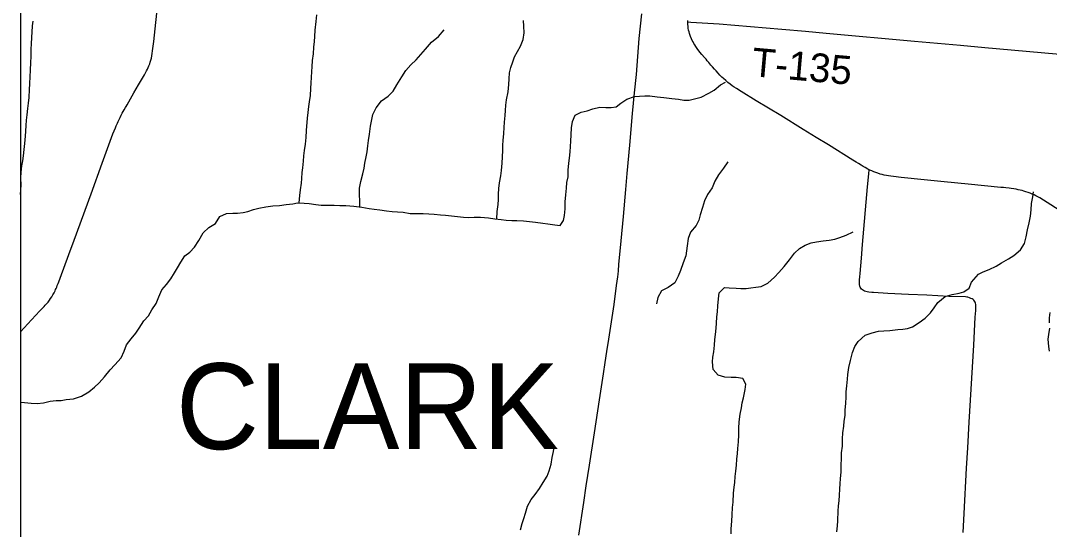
# Model space of a CAD drawing. Extents: x 0 to 48.6, y 0 to 22.
# Drawn here: x 2.1 to 4.141, y 18.455 to 19.466 of the extents above; entities that cross this region are included whole.
import ezdxf

# ---------------------------------------------------------------- set-up
doc = ezdxf.new("R2010")
doc.units = 0
for name, color, linetype in [('GM_X_Corporation', 7, 'Continuous'), ('GM_X_County_Road', 7, 'Continuous'), ('GM_X_Minor_River', 7, 'Continuous'), ('GM_X_State_Route', 7, 'Continuous'), ('GM_X_Township_Road', 7, 'Continuous'), ('GM_X_Township_Road_Text', 7, 'Continuous'), ('GM_X_Township_Text', 7, 'Continuous'), ('SH_Data', 7, 'Continuous')]:
    doc.layers.add(name, color=color, linetype=linetype)

msp = doc.modelspace()

# ---------------------------------------------------------------- linework, layer by layer
at = {"layer": 'GM_X_Corporation'}
for points in [[(8.9, 20.9), (2.1, 20.9), (2.1, 14.1)], [(5.5264, 17.0064), (5.8387, 17.2541), (6.5365, 17.7727), (6.4996, 17.9212), (6.3396, 18.6531), (6.2759, 18.9159), (6.0412, 19.8859), (5.8236, 20.7829), (5.795, 20.9), (2.1, 20.9), (2.1, 14.1)]]:
    msp.add_lwpolyline(points, dxfattribs=at)
at = {"layer": 'GM_X_County_Road'}
for points in [[(2.1, 18.8478), (2.1219, 18.8718), (2.1303, 18.881), (2.1376, 18.8886), (2.1467, 18.8983), (2.1487, 18.9004), (2.1514, 18.9035), (2.1544, 18.9069), (2.1572, 18.9107), (2.1595, 18.9138), (2.1619, 18.9174), (2.1642, 18.921), (2.1652, 18.9229), (2.1663, 18.925), (2.1686, 18.9292), (2.1695, 18.9315), (2.1705, 18.9337), (2.1716, 18.9362), (2.1729, 18.9394), (2.1745, 18.9436), (2.1757, 18.9468), (2.1786, 18.9545), (2.1958, 19.0012), (2.2062, 19.0298), (2.2401, 19.1219), (2.2618, 19.1828), (2.2832, 19.2405), (2.288, 19.2526), (2.2896, 19.2567), (2.2921, 19.2622), (2.2934, 19.265), (2.2947, 19.2681), (2.2973, 19.2732), (2.2998, 19.2781), (2.3017, 19.2816), (2.3037, 19.2852), (2.3054, 19.2883), (2.3079, 19.2928), (2.3093, 19.2953), (2.3112, 19.2985), (2.3245, 19.322), (2.334, 19.338), (2.3457, 19.3578), (2.3501, 19.366), (2.3517, 19.3693), (2.3533, 19.3726), (2.3547, 19.376), (2.3561, 19.3795), (2.3573, 19.3831), (2.3585, 19.3871), (2.3595, 19.3913), (2.3604, 19.3955), (2.3612, 19.4005), (2.362, 19.4053), (2.3641, 19.4238), (2.368, 19.4615), (2.374, 19.5171)], [(3.2071, 18.4437), (3.217, 18.5088), (3.222, 18.542), (3.2283, 18.5831), (3.2382, 18.6469), (3.2483, 18.7127), (3.2561, 18.7643), (3.2597, 18.787), (3.2628, 18.8085), (3.2667, 18.8331), (3.2771, 18.9019), (3.2823, 18.9394), (3.2845, 18.9571), (3.2851, 18.9622), (3.2857, 18.9687), (3.287, 18.9813), (3.291, 19.0284), (3.2956, 19.0766), (3.3005, 19.1304), (3.3034, 19.162), (3.3085, 19.2183), (3.3141, 19.2814), (3.318, 19.3222), (3.3215, 19.3587), (3.3273, 19.4298), (3.332, 19.4793)], [(3.9697, 18.4493), (3.9718, 18.4871), (3.9766, 18.5771), (3.979, 18.6174), (3.9818, 18.6683), (3.9906, 18.8209), (3.9936, 18.8767), (3.9946, 18.8898), (3.9948, 18.8948), (3.9949, 18.8986), (3.9946, 18.9019), (3.9941, 18.9046), (3.9933, 18.9069), (3.9923, 18.9087), (3.9907, 18.9104), (3.9893, 18.9117), (3.9874, 18.913), (3.9852, 18.9142), (3.9822, 18.9154), (3.9792, 18.9162), (3.9768, 18.9166), (3.9741, 18.9169), (3.941, 18.9181), (3.8976, 18.9204), (3.861, 18.9221), (3.82, 18.924), (3.7921, 18.9256), (3.7884, 18.9258), (3.7828, 18.9264), (3.7792, 18.9269), (3.7764, 18.9276), (3.7738, 18.9285), (3.7719, 18.9296), (3.7701, 18.9309), (3.7683, 18.9325), (3.7666, 18.9347), (3.7657, 18.9366), (3.7649, 18.9385), (3.7643, 18.9414), (3.7642, 18.9433), (3.7639, 18.9456), (3.764, 18.9487), (3.7641, 18.9512), (3.7646, 18.9567), (3.7653, 18.9635), (3.7679, 18.9938), (3.7702, 19.021), (3.78, 19.1355), (3.7827, 19.1615), (3.7835, 19.1695)]]:
    msp.add_lwpolyline(points, dxfattribs=at)
at = {"layer": 'GM_X_Minor_River'}
for points in [[(2.6523, 19.1036), (2.6537, 19.1181), (2.6554, 19.1298), (2.6571, 19.1427), (2.6579, 19.1522), (2.6585, 19.1639), (2.6597, 19.1734), (2.6611, 19.1863), (2.6616, 19.1969), (2.6632, 19.2079), (2.6649, 19.2204), (2.6662, 19.2333), (2.6672, 19.2473), (2.6694, 19.272), (2.6707, 19.2833), (2.672, 19.2951), (2.6733, 19.3046), (2.6749, 19.3167), (2.6759, 19.3311), (2.6764, 19.3421), (2.6769, 19.3527), (2.6775, 19.3645), (2.6784, 19.374), (2.6793, 19.3865), (2.681, 19.3994), (2.6815, 19.413), (2.6828, 19.4244), (2.6837, 19.4339), (2.6846, 19.4464), (2.6864, 19.4635), (2.6877, 19.4767)], [(2.1, 19.1202), (2.1008, 19.1294), (2.1009, 19.1389), (2.1007, 19.1533), (2.1013, 19.1639), (2.1026, 19.1772), (2.1046, 19.187), (2.1055, 19.1973), (2.1068, 19.2094), (2.1085, 19.2219), (2.1098, 19.2359), (2.1107, 19.2458), (2.1112, 19.2576), (2.1118, 19.2682), (2.113, 19.2784), (2.1144, 19.2913), (2.1156, 19.3015), (2.1169, 19.3129), (2.1175, 19.3289), (2.1184, 19.3402), (2.119, 19.3546), (2.1195, 19.3668), (2.1201, 19.3831), (2.1207, 19.3937), (2.1212, 19.4093), (2.1217, 19.4188), (2.1223, 19.4324), (2.1228, 19.4423), (2.1238, 19.4552), (2.125, 19.4647)], [(3.0445, 19.0717), (3.0453, 19.0864), (3.047, 19.1004), (3.0479, 19.1103), (3.048, 19.1213), (3.0485, 19.1323), (3.0502, 19.1437), (3.0523, 19.1577), (3.0539, 19.1683), (3.0553, 19.1823), (3.0562, 19.1948), (3.0567, 19.2077), (3.0569, 19.218), (3.0574, 19.2275), (3.0583, 19.2415), (3.0589, 19.2533), (3.0598, 19.2639), (3.0615, 19.2775), (3.062, 19.287), (3.0625, 19.2976), (3.0638, 19.3083), (3.067, 19.3242), (3.0687, 19.3389), (3.0689, 19.3503), (3.0698, 19.3617), (3.0722, 19.3727), (3.0762, 19.3836), (3.0797, 19.3938), (3.0856, 19.404), (3.0914, 19.4146), (3.0969, 19.4278), (3.0986, 19.4414), (3.098, 19.4547), (3.0978, 19.4657)], [(2.773, 19.0957), (2.7732, 19.1078), (2.7726, 19.1199), (2.7724, 19.1332), (2.7748, 19.1461), (2.7792, 19.1616), (2.7813, 19.1726), (2.7829, 19.1828), (2.7858, 19.1949), (2.7874, 19.2048), (2.7891, 19.2169), (2.7904, 19.2275), (2.792, 19.24), (2.7942, 19.2559), (2.7962, 19.2662), (2.799, 19.279), (2.8053, 19.2926), (2.8157, 19.3061), (2.8291, 19.3158), (2.8388, 19.3256), (2.8465, 19.338), (2.8562, 19.3538), (2.8644, 19.3666), (2.874, 19.3775), (2.8844, 19.388), (2.8937, 19.3981), (2.9029, 19.4087), (2.9153, 19.4225), (2.9287, 19.4341), (2.9399, 19.4473)], [(3.1772, 19.0688), (3.1789, 19.0786), (3.1802, 19.0919), (3.1804, 19.1059), (3.1813, 19.12), (3.1826, 19.1332), (3.1835, 19.1442), (3.1859, 19.1552), (3.1865, 19.1689), (3.1878, 19.1825), (3.1891, 19.1924), (3.19, 19.2053), (3.1909, 19.2159), (3.1914, 19.2261), (3.192, 19.239), (3.1926, 19.2527), (3.1946, 19.2652), (3.2001, 19.278), (3.212, 19.2839), (3.2238, 19.2864), (3.2348, 19.2901), (3.2493, 19.2937), (3.2607, 19.2932), (3.2713, 19.293), (3.2812, 19.2944), (3.2908, 19.3019), (3.3027, 19.3093), (3.318, 19.3148), (3.3279, 19.3158), (3.3385, 19.3161), (3.3484, 19.316), (3.3628, 19.3142), (3.3761, 19.3126), (3.3916, 19.3112), (3.4049, 19.3095), (3.4155, 19.3079), (3.4261, 19.3077), (3.4391, 19.3106), (3.4501, 19.3135), (3.4654, 19.3213), (3.4758, 19.3276), (3.4881, 19.3381), (3.498, 19.3436)], [(3.5027, 19.1853), (3.4942, 19.1725), (3.4842, 19.1597), (3.4772, 19.1469), (3.4717, 19.1333), (3.4628, 19.1205), (3.4565, 19.1077), (3.4525, 19.0948), (3.4482, 19.0801), (3.4454, 19.0695), (3.4399, 19.0585), (3.4291, 19.0458), (3.424, 19.0333), (3.4219, 19.0185), (3.4206, 19.0087), (3.4194, 18.9988), (3.4142, 18.9845), (3.4087, 18.9697), (3.4044, 18.958), (3.3978, 18.9452), (3.3847, 18.9359), (3.371, 18.9288), (3.364, 18.9156), (3.3615, 18.9035)], [(3.7354, 18.6819), (3.7359, 18.6925), (3.7368, 18.7062), (3.7374, 18.7179), (3.7379, 18.7286), (3.7392, 18.7403), (3.7401, 18.7536), (3.7406, 18.7631), (3.7431, 18.7767), (3.7463, 18.7907), (3.7499, 18.8066), (3.755, 18.8183), (3.7616, 18.8285), (3.7751, 18.8412), (3.7892, 18.846), (3.8018, 18.8492), (3.8124, 18.8498), (3.8242, 18.8504), (3.8398, 18.8521), (3.8497, 18.8532), (3.8592, 18.8545), (3.8691, 18.8575), (3.8822, 18.866), (3.894, 18.875), (3.9048, 18.8855), (3.9122, 18.8952), (3.9191, 18.9058), (3.9337, 18.9181), (3.9478, 18.9221), (3.9615, 18.9242), (3.9711, 18.9271), (3.9814, 18.9346), (3.9865, 18.9463), (4, 18.9621), (4.0096, 18.9669), (4.0214, 18.9716), (4.0352, 18.9779), (4.0459, 18.9846), (4.0593, 18.9924), (4.07, 18.9991), (4.0831, 19.0107), (4.0912, 19.0231), (4.0945, 19.0364), (4.0973, 19.0504), (4.1009, 19.064), (4.103, 19.0773), (4.1047, 19.0898), (4.1052, 19.1023), (4.1077, 19.1159), (4.1089, 19.1254)], [(2.1, 18.7078), (2.1077, 18.7072), (2.121, 18.7058), (2.1328, 18.7057), (2.1457, 18.707), (2.1587, 18.7099), (2.1708, 18.7117), (2.1807, 18.7115), (2.1902, 18.7133), (2.2051, 18.715), (2.2207, 18.7197), (2.2352, 18.7283), (2.2464, 18.738), (2.256, 18.7466), (2.2664, 18.7586), (2.2776, 18.7725), (2.2872, 18.7819), (2.2996, 18.7958), (2.3055, 18.8094), (2.3098, 18.8218), (2.3191, 18.8339), (2.3283, 18.8448), (2.3353, 18.8549), (2.3442, 18.8696), (2.3539, 18.8797), (2.3601, 18.8914), (2.369, 18.9042), (2.3741, 18.9174), (2.3804, 18.931), (2.3893, 18.9415), (2.3981, 18.9528), (2.4055, 18.9645), (2.4114, 18.975), (2.418, 18.986), (2.4257, 18.9984), (2.4357, 19.0059), (2.4453, 19.0156), (2.4539, 19.0292), (2.4624, 19.0442), (2.4736, 19.0547), (2.4866, 19.0625), (2.4951, 19.0765), (2.5085, 19.0827), (2.5207, 19.0833), (2.5305, 19.0832), (2.5412, 19.0846), (2.5507, 19.0867), (2.5622, 19.0904), (2.5725, 19.0929), (2.5865, 19.0958), (2.6002, 19.0979), (2.6139, 19.0985), (2.6269, 19.1002), (2.6398, 19.1015), (2.6493, 19.1037), (2.6626, 19.1031), (2.6725, 19.1023), (2.6857, 19.1006), (2.6964, 19.0993), (2.7222, 19.0989), (2.7332, 19.0984), (2.7453, 19.0983), (2.7613, 19.0969), (2.7772, 19.0952), (2.7912, 19.0927), (2.8011, 19.0915), (2.8125, 19.0902), (2.8257, 19.0881), (2.8371, 19.0868), (2.8477, 19.0859), (2.8587, 19.085), (2.8731, 19.0829), (2.8853, 19.0824), (2.8986, 19.0826), (2.91, 19.0817), (2.9206, 19.0812), (2.9327, 19.0803), (2.943, 19.079), (2.9547, 19.0781), (2.9665, 19.0764), (2.9783, 19.0755), (2.9893, 19.075), (2.9999, 19.0752), (3.0124, 19.0754), (3.028, 19.0741), (3.0409, 19.072), (3.0534, 19.0707), (3.0629, 19.0695), (3.0746, 19.0686), (3.0845, 19.0684), (3.0978, 19.0679), (3.1092, 19.067), (3.1213, 19.0657), (3.1357, 19.0632), (3.1456, 19.0623), (3.1596, 19.0603), (3.1706, 19.059), (3.1772, 19.0688)], [(3.5393, 18.9339), (3.5488, 18.9349), (3.5587, 18.9366), (3.569, 18.938), (3.582, 18.9443), (3.5954, 18.9559), (3.6043, 18.9657), (3.6147, 18.9777), (3.6255, 18.9908), (3.6348, 19.004), (3.6448, 19.0134), (3.6563, 19.02), (3.6681, 19.0241), (3.6788, 19.0266), (3.6917, 19.0283), (3.7039, 19.03), (3.7149, 19.0314), (3.7252, 19.0347), (3.7378, 19.0399), (3.7516, 19.0465)], [(3.5093, 18.4464), (3.5098, 18.4563), (3.5107, 18.4715), (3.5113, 18.4844), (3.5119, 18.4988), (3.5132, 18.5098), (3.5141, 18.5272), (3.5154, 18.539), (3.5167, 18.5485), (3.5176, 18.5606), (3.5189, 18.5708), (3.5202, 18.5833), (3.5207, 18.5951), (3.522, 18.6061), (3.5225, 18.6163), (3.5239, 18.6292), (3.5248, 18.6433), (3.5246, 18.6565), (3.5251, 18.6687), (3.5276, 18.6842), (3.5297, 18.6967), (3.5313, 18.7066), (3.5338, 18.7164), (3.537, 18.7334), (3.5383, 18.7437), (3.5324, 18.7551), (3.5191, 18.7568), (3.5096, 18.757), (3.4967, 18.7579), (3.4838, 18.7619), (3.4737, 18.773), (3.4724, 18.7882), (3.4733, 18.7977), (3.475, 18.8083), (3.4763, 18.8215), (3.4768, 18.8322), (3.4781, 18.8424), (3.4798, 18.8549), (3.4807, 18.8651), (3.4812, 18.8773), (3.4821, 18.8875), (3.483, 18.8993), (3.4843, 18.9129), (3.486, 18.9251), (3.496, 18.9356), (3.5055, 18.9351), (3.5192, 18.9345), (3.5287, 18.934), (3.5393, 18.9339)], [(4.1412, 18.8653), (4.1406, 18.8756), (4.1422, 18.8862)], [(4.1408, 18.8091), (4.1394, 18.8187), (4.1381, 18.8331), (4.1394, 18.8426), (4.1418, 18.8547)], [(3.719, 18.4509), (3.7203, 18.4623), (3.7212, 18.4722), (3.7215, 18.4923), (3.7223, 18.5018), (3.7236, 18.5127), (3.7241, 18.523), (3.7251, 18.5363), (3.726, 18.5457), (3.7265, 18.5567), (3.7278, 18.5689), (3.7276, 18.5844), (3.7281, 18.5951), (3.7283, 18.6072), (3.73, 18.6205), (3.7306, 18.6353), (3.7311, 18.6474), (3.7328, 18.6603), (3.7337, 18.6702), (3.7354, 18.6819)], [(3.0919, 18.4549), (3.0951, 18.467), (3.0983, 18.4768), (3.1015, 18.4878), (3.1058, 18.5014), (3.1125, 18.5146), (3.1206, 18.5247), (3.1291, 18.5368), (3.1369, 18.5484), (3.1442, 18.5609), (3.1486, 18.5718), (3.1525, 18.5851), (3.1542, 18.5983), (3.1571, 18.6101), (3.1583, 18.6199)]]:
    msp.add_lwpolyline(points, dxfattribs=at)
at = {"layer": 'GM_X_State_Route'}
msp.add_lwpolyline([(4.1604, 19.0894), (4.1362, 19.1047), (4.1219, 19.1134), (4.1179, 19.1155), (4.1137, 19.1178), (4.1103, 19.1194), (4.1065, 19.1212), (4.1024, 19.1228), (4.0985, 19.1244), (4.0939, 19.1259), (4.0902, 19.127), (4.0865, 19.128), (4.0825, 19.1291), (4.079, 19.1298), (4.0746, 19.1307), (4.0699, 19.1314), (4.0649, 19.1322), (4.0606, 19.1327), (4.0545, 19.1334), (4.0495, 19.134), (4.0442, 19.1345), (3.9796, 19.1408), (3.932, 19.1455), (3.8924, 19.1496), (3.8467, 19.1541), (3.8318, 19.1558), (3.8265, 19.1566), (3.8213, 19.1573), (3.8176, 19.158), (3.8133, 19.1588), (3.8091, 19.1598), (3.8048, 19.1609), (3.8002, 19.1624), (3.7965, 19.1637), (3.7926, 19.1653), (3.7884, 19.167), (3.7848, 19.1688), (3.7835, 19.1695), (3.7806, 19.1709), (3.7755, 19.1737), (3.7713, 19.176), (3.7674, 19.1784), (3.7618, 19.1818), (3.7574, 19.1844), (3.7508, 19.1885), (3.7027, 19.2187), (3.6783, 19.2337), (3.6524, 19.2496), (3.6079, 19.2769), (3.5591, 19.3066), (3.5293, 19.3246), (3.5198, 19.3305), (3.5153, 19.3336), (3.5115, 19.3361), (3.5074, 19.3393), (3.5031, 19.3426), (3.4989, 19.3464), (3.4943, 19.3505), (3.4911, 19.3536), (3.4871, 19.3575), (3.4836, 19.3613), (3.4795, 19.3657), (3.4766, 19.369), (3.4726, 19.3736), (3.4692, 19.3774), (3.4649, 19.3825), (3.462, 19.3859), (3.4596, 19.3888), (3.4565, 19.3925), (3.4516, 19.3983), (3.4476, 19.4031), (3.4419, 19.4105), (3.4394, 19.4143), (3.4373, 19.4172), (3.4354, 19.4204), (3.4338, 19.4231), (3.4321, 19.4264), (3.4306, 19.4293), (3.4287, 19.4339), (3.4266, 19.4399), (3.4259, 19.4431), (3.425, 19.4466), (3.4244, 19.4503), (3.424, 19.4545), (3.4237, 19.4578), (3.4237, 19.4623), (3.4237, 19.4632), (3.4237, 19.466)], dxfattribs=at)
at = {"layer": 'GM_X_Township_Road'}
msp.add_lwpolyline([(3.4237, 19.4632), (3.4298, 19.4628), (3.4858, 19.4592), (3.6097, 19.4486), (3.6567, 19.4445), (3.6982, 19.4408), (3.8734, 19.4248), (3.9644, 19.417), (4.0125, 19.4121), (4.1842, 19.3971), (4.2813, 19.3892), (4.3215, 19.3858), (4.3667, 19.3818), (4.4521, 19.374), (4.5746, 19.3634), (4.6862, 19.3527), (4.6878, 19.3526)], dxfattribs=at)
at = {"layer": 'SH_Data'}
msp.add_line((2.1, 20.9), (2.1, 14.1), dxfattribs=at)

# ---------------------------------------------------------------- texts
at = {"layer": 'GM_X_Township_Road_Text'}
msp.add_text('T-135', height=0.05682, rotation=354.957, dxfattribs=at).set_placement((3.5487, 19.3554))
at = {"layer": 'GM_X_Township_Text'}
msp.add_text('CLARK', height=0.17045, rotation=0, dxfattribs=at).set_placement((2.4082, 18.6148))

doc.saveas('drawing.dxf')
